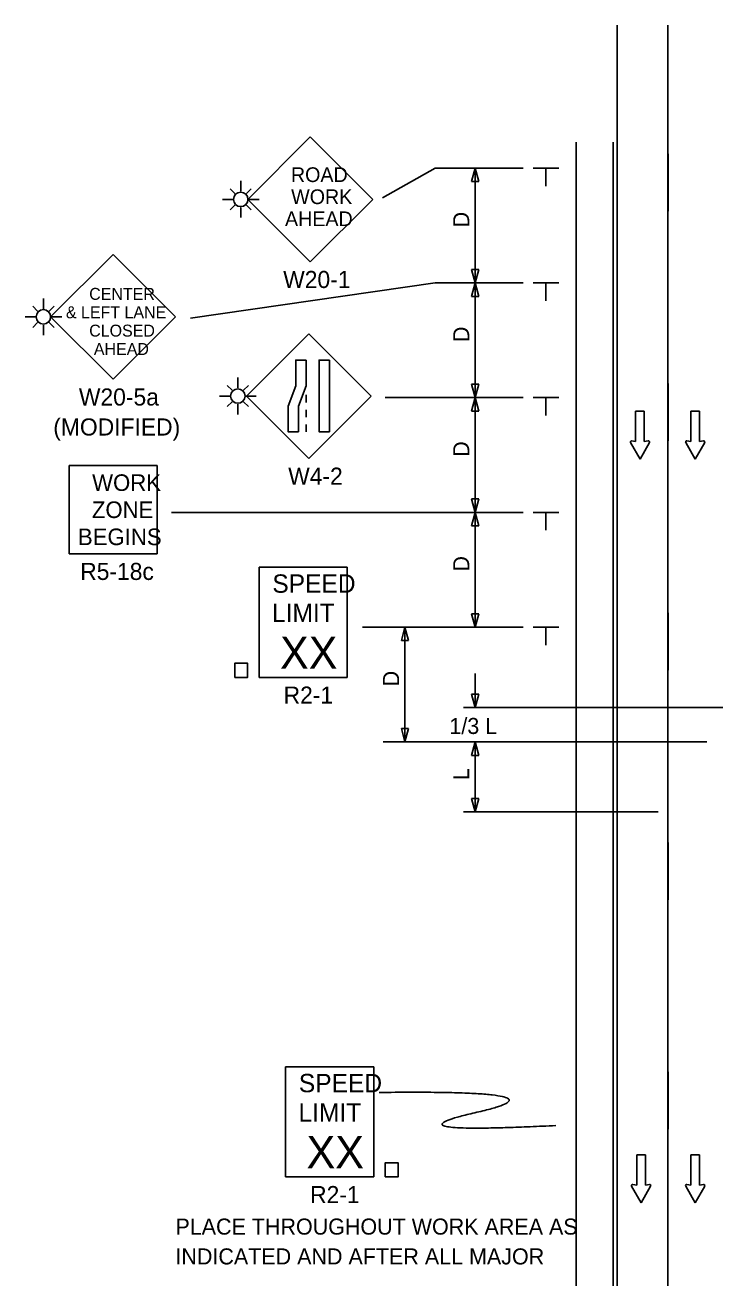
# Model space of a CAD drawing. Extents: x 16038 to 19504, y 5920 to 8321.
# Drawn here: x 16730 to 17031, y 7716 to 8262 of the extents above; entities that cross this region are included whole.
import ezdxf

# ---------------------------------------------------------------- set-up
doc = ezdxf.new("R2010")
doc.units = 0
for name, color, linetype in [('ALI_LEGAL_EX', 7, 'Continuous'), ('MT_SCRATCH_LEVEL_E', 7, 'Continuous'), ('PAVT_EDGE_EX', 7, 'Continuous'), ('TRAFFIC_SIGNS_PR', 7, 'Continuous'), ('TYPICAL_TEXT_DIMEN_PR', 7, 'Continuous')]:
    doc.layers.add(name, color=color, linetype=linetype)

msp = doc.modelspace()

# ---------------------------------------------------------------- linework, layer by layer
at = {"layer": 'ALI_LEGAL_EX'}
for points in [[(17010.3, 8181.21), (17010.3, 8206.21)], [(17010.3, 8081.21), (17010.3, 8106.21)], [(17010.3, 7981.21), (17010.3, 8006.21)], [(17010.3, 7881.21), (17010.3, 7906.21)], [(17010.3, 7781.21), (17010.3, 7806.21)]]:
    msp.add_lwpolyline(points, dxfattribs=at)
at = {"layer": 'MT_SCRATCH_LEVEL_E'}
for p, q in [((16999.9, 8094.07), (16996.16, 8094.07)), ((16996.16, 8094.07), (16996.16, 8080.81)), ((16999.9, 8094.07), (16996.16, 8094.07)), ((16996.16, 8094.07), (16996.16, 8080.81)), ((16999.9, 8080.81), (16999.9, 8094.07)), ((16999.9, 8080.81), (16999.9, 8094.07)), ((17023.97, 8094.07), (17020.23, 8094.07)), ((17020.23, 8094.07), (17020.23, 8080.81)), ((17023.97, 8094.07), (17020.23, 8094.07)), ((17020.23, 8094.07), (17020.23, 8080.81)), ((17023.97, 8094.07), (17020.23, 8094.07)), ((17020.23, 8094.07), (17020.23, 8080.81)), ((17023.97, 8094.07), (17020.23, 8094.07)), ((17020.23, 8094.07), (17020.23, 8080.81)), ((17023.97, 8080.81), (17023.97, 8094.07)), ((17023.97, 8080.81), (17023.97, 8094.07)), ((17023.97, 8080.81), (17023.97, 8094.07)), ((17023.97, 8080.81), (17023.97, 8094.07)), ((16993.9, 8080.44), (16998.05, 8073.2)), ((16993.9, 8080.44), (16998.05, 8073.2)), ((16996.16, 8080.81), (16994.38, 8081.12)), ((16996.16, 8080.81), (16994.38, 8081.12)), ((16998.05, 8073.2), (17002.16, 8080.44)), ((16998.05, 8073.2), (17002.16, 8080.44)), ((17001.68, 8081.12), (16999.9, 8080.81)), ((17001.68, 8081.12), (16999.9, 8080.81)), ((17017.97, 8080.44), (17022.12, 8073.2)), ((17017.97, 8080.44), (17022.12, 8073.2)), ((17017.97, 8080.44), (17022.12, 8073.2)), ((17017.97, 8080.44), (17022.12, 8073.2)), ((17020.23, 8080.81), (17018.45, 8081.12)), ((17020.23, 8080.81), (17018.45, 8081.12)), ((17020.23, 8080.81), (17018.45, 8081.12)), ((17020.23, 8080.81), (17018.45, 8081.12)), ((17022.12, 8073.2), (17026.23, 8080.44)), ((17022.12, 8073.2), (17026.23, 8080.44)), ((17022.12, 8073.2), (17026.23, 8080.44)), ((17022.12, 8073.2), (17026.23, 8080.44)), ((17025.75, 8081.12), (17023.97, 8080.81)), ((17025.75, 8081.12), (17023.97, 8080.81)), ((17025.75, 8081.12), (17023.97, 8080.81)), ((17025.75, 8081.12), (17023.97, 8080.81)), ((17000.4, 7770.06), (16996.66, 7770.06)), ((16996.66, 7770.06), (16996.66, 7756.81)), ((17000.4, 7770.06), (16996.66, 7770.06)), ((16996.66, 7770.06), (16996.66, 7756.81)), ((17000.4, 7756.81), (17000.4, 7770.06)), ((17000.4, 7756.81), (17000.4, 7770.06)), ((17023.97, 7770.06), (17020.23, 7770.06)), ((17020.23, 7770.06), (17020.23, 7756.81)), ((17023.97, 7770.06), (17020.23, 7770.06)), ((17020.23, 7770.06), (17020.23, 7756.81)), ((17023.97, 7756.81), (17023.97, 7770.06)), ((17023.97, 7756.81), (17023.97, 7770.06)), ((16994.4, 7756.44), (16998.55, 7749.2)), ((16994.4, 7756.44), (16998.55, 7749.2)), ((16996.66, 7756.81), (16994.88, 7757.12)), ((16996.66, 7756.81), (16994.88, 7757.12)), ((16998.55, 7749.2), (17002.66, 7756.44)), ((16998.55, 7749.2), (17002.66, 7756.44)), ((17002.18, 7757.12), (17000.4, 7756.81)), ((17002.18, 7757.12), (17000.4, 7756.81)), ((17017.97, 7756.44), (17022.12, 7749.2)), ((17017.97, 7756.44), (17022.12, 7749.2)), ((17020.23, 7756.81), (17018.45, 7757.12)), ((17020.23, 7756.81), (17018.45, 7757.12)), ((17022.12, 7749.2), (17026.23, 7756.44)), ((17022.12, 7749.2), (17026.23, 7756.44)), ((17025.75, 7757.12), (17023.97, 7756.81)), ((17025.75, 7757.12), (17023.97, 7756.81))]:
    msp.add_line(p, q, dxfattribs=at)
for centre, start, end in [((16994.31, 8080.67), 80.0362, 209.7731), ((16994.31, 8080.67), 80.0362, 209.7731), ((17001.75, 8080.67), 330.4248, 99.9638), ((17001.75, 8080.67), 330.4248, 99.9638), ((17018.38, 8080.67), 80.0362, 209.7731), ((17018.38, 8080.67), 80.0362, 209.7731), ((17018.38, 8080.67), 80.0362, 209.7731), ((17018.38, 8080.67), 80.0362, 209.7731), ((17025.82, 8080.67), 330.4248, 99.9638), ((17025.82, 8080.67), 330.4248, 99.9638), ((17025.82, 8080.67), 330.4248, 99.9638), ((17025.82, 8080.67), 330.4248, 99.9638), ((16994.81, 7756.66), 80.0362, 209.7731), ((16994.81, 7756.66), 80.0362, 209.7731), ((17002.25, 7756.66), 330.4248, 99.9638), ((17002.25, 7756.66), 330.4248, 99.9638), ((17018.38, 7756.66), 80.0362, 209.7731), ((17018.38, 7756.66), 80.0362, 209.7731), ((17025.82, 7756.66), 330.4248, 99.9638), ((17025.82, 7756.66), 330.4248, 99.9638)]:
    msp.add_arc(centre, 0.463, start, end, dxfattribs=at)
at = {"layer": 'PAVT_EDGE_EX'}
for p, q in [((16988.15, 8262.34), (16988.15, 7433.15)), ((17010.15, 8262.34), (17010.15, 7433.15)), ((16970.3, 8211.37), (16970.3, 7379.53)), ((16986.3, 8211.37), (16986.3, 7379.53))]:
    msp.add_line(p, q, dxfattribs=at)
at = {"layer": 'TRAFFIC_SIGNS_PR'}
for p, q in [((16854.39, 8213.58), (16827.2, 8186.39)), ((16881.58, 8186.39), (16854.39, 8213.58)), ((16821.54, 8188.91), (16819.43, 8191.02)), ((16824.05, 8189.95), (16824.05, 8194.45)), ((16826.56, 8188.91), (16828.67, 8191.02)), ((16820.9, 8186.39), (16816.06, 8186.39)), ((16821.54, 8183.88), (16819.43, 8181.77)), ((16826.56, 8183.88), (16828.67, 8181.77)), ((16827.2, 8186.39), (16854.39, 8159.21)), ((16827.2, 8186.39), (16832.09, 8186.39)), ((16854.39, 8159.21), (16881.58, 8186.39)), ((16824.05, 8178.43), (16824.05, 8182.84)), ((16768.41, 8162.37), (16741.22, 8135.18)), ((16795.59, 8135.18), (16768.41, 8162.37)), ((16738.07, 8138.74), (16738.07, 8143.24)), ((16734.91, 8135.18), (16730.08, 8135.18)), ((16735.55, 8137.69), (16733.44, 8139.8)), ((16740.58, 8137.69), (16742.69, 8139.8)), ((16741.22, 8135.18), (16768.41, 8107.99)), ((16741.22, 8135.18), (16746.1, 8135.18)), ((16741.22, 8135.18), (16768.41, 8107.99)), ((16768.41, 8107.99), (16795.59, 8135.18)), ((16735.55, 8132.67), (16733.44, 8130.56)), ((16738.07, 8127.22), (16738.07, 8131.63)), ((16740.58, 8132.67), (16742.69, 8130.56)), ((16853.78, 8127.8), (16826.63, 8100.65)), ((16880.93, 8100.65), (16853.78, 8127.8)), ((16822.8, 8104.24), (16822.8, 8108.74)), ((16820.29, 8103.19), (16818.18, 8105.3)), ((16825.31, 8103.19), (16827.42, 8105.3)), ((16819.65, 8100.68), (16814.81, 8100.68)), ((16820.29, 8098.17), (16818.18, 8096.06)), ((16822.8, 8092.71), (16822.8, 8097.13)), ((16825.31, 8098.17), (16827.42, 8096.06)), ((16825.96, 8100.68), (16830.84, 8100.68)), ((16826.63, 8100.65), (16853.78, 8073.49)), ((16852.53, 8101.14), (16852.53, 8097.94)), ((16853.78, 8073.49), (16880.93, 8100.65)), ((16852.53, 8094.74), (16852.53, 8091.54)), ((16852.53, 8088.34), (16852.53, 8085.14)), ((16749.31, 8031.98), (16749.31, 8070.38)), ((16749.31, 8070.38), (16787.71, 8070.38)), ((16787.71, 8031.98), (16787.71, 8070.38)), ((16749.31, 8031.98), (16787.71, 8031.98)), ((16832.07, 8026.1), (16870.47, 8026.1)), ((16832.07, 7978.1), (16832.07, 8026.1)), ((16870.47, 7978.1), (16870.47, 8026.1)), ((16832.07, 7978.1), (16870.47, 7978.1)), ((16843.62, 7808.45), (16882.02, 7808.45)), ((16843.62, 7760.45), (16843.62, 7808.45)), ((16882.02, 7760.45), (16882.02, 7808.45)), ((16843.62, 7760.45), (16882.02, 7760.45))]:
    msp.add_line(p, q, dxfattribs=at)
for points in [[(16852.53, 8116.38), (16852.53, 8105.2), (16849.19, 8096.32), (16849.19, 8085.14), (16844.69, 8085.14), (16844.69, 8096.32), (16848.04, 8105.2), (16848.04, 8116.38)], [(16862.67, 8116.38), (16862.67, 8085.14), (16858.18, 8085.14), (16858.18, 8116.38)], [(16821.46, 7978.1), (16827.05, 7978.1), (16827.05, 7984.27), (16821.46, 7984.27)], [(16887.04, 7760.45), (16892.63, 7760.45), (16892.63, 7766.63), (16887.04, 7766.63)]]:
    msp.add_lwpolyline(points, close=True, dxfattribs=at)
for centre in [(16824.05, 8186.39), (16738.07, 8135.18), (16822.8, 8100.68)]:
    msp.add_circle(centre, 3.15, dxfattribs=at)
msp.add_open_spline([(16884.36, 7797.22), (16969.4, 7798.24), (16884.38, 7778.89), (16961.38, 7782.81)], degree=2, dxfattribs=at)
at = {"layer": 'TYPICAL_TEXT_DIMEN_PR'}
for p, q in [((16908.76, 8199.98), (16885.9, 8187.11)), ((16908.76, 8199.98), (16947.2, 8199.98)), ((16924.63, 8194.11), (16926.2, 8199.98)), ((16924.63, 8194.11), (16926.2, 8199.98)), ((16926.2, 8199.98), (16927.77, 8194.11)), ((16926.2, 8199.98), (16927.77, 8194.11)), ((16926.2, 8149.98), (16926.2, 8199.98)), ((16951.45, 8199.98), (16962.7, 8199.98)), ((16951.45, 8199.98), (16962.7, 8199.98)), ((16957.08, 8199.98), (16957.08, 8192.19)), ((16957.08, 8199.98), (16957.08, 8192.19)), ((16926.2, 8194.11), (16924.63, 8194.11)), ((16926.2, 8194.11), (16924.63, 8194.11)), ((16927.77, 8194.11), (16926.2, 8194.11)), ((16927.77, 8194.11), (16926.2, 8194.11)), ((16926.2, 8149.98), (16924.63, 8155.84)), ((16924.63, 8155.84), (16926.2, 8155.84)), ((16926.2, 8149.98), (16924.63, 8155.84)), ((16924.63, 8155.84), (16926.2, 8155.84)), ((16926.2, 8155.84), (16927.77, 8155.84)), ((16927.77, 8155.84), (16926.2, 8149.98)), ((16926.2, 8155.84), (16927.77, 8155.84)), ((16927.77, 8155.84), (16926.2, 8149.98)), ((16908.76, 8149.98), (16802.1, 8134.61)), ((16908.76, 8149.98), (16947.2, 8149.98)), ((16924.63, 8144.11), (16926.2, 8149.98)), ((16924.63, 8144.11), (16926.2, 8149.98)), ((16926.2, 8149.98), (16927.77, 8144.11)), ((16926.2, 8149.98), (16927.77, 8144.11)), ((16926.2, 8099.98), (16926.2, 8149.98)), ((16951.45, 8149.98), (16962.7, 8149.98)), ((16957.08, 8149.98), (16957.08, 8142.19)), ((16926.2, 8144.11), (16924.63, 8144.11)), ((16926.2, 8144.11), (16924.63, 8144.11)), ((16927.77, 8144.11), (16926.2, 8144.11)), ((16927.77, 8144.11), (16926.2, 8144.11)), ((16926.2, 8099.98), (16924.63, 8105.84)), ((16924.63, 8105.84), (16926.2, 8105.84)), ((16926.2, 8105.84), (16927.77, 8105.84)), ((16927.77, 8105.84), (16926.2, 8099.98)), ((16886.97, 8099.98), (16947.2, 8099.98)), ((16924.63, 8094.11), (16926.2, 8099.98)), ((16924.63, 8094.11), (16926.2, 8099.98)), ((16926.2, 8099.98), (16927.77, 8094.11)), ((16926.2, 8099.98), (16927.77, 8094.11)), ((16926.2, 8049.98), (16926.2, 8099.98)), ((16951.45, 8099.98), (16962.7, 8099.98)), ((16951.45, 8099.98), (16962.7, 8099.98)), ((16957.08, 8099.98), (16957.08, 8092.19)), ((16957.08, 8099.98), (16957.08, 8092.19)), ((16926.2, 8094.11), (16924.63, 8094.11)), ((16926.2, 8094.11), (16924.63, 8094.11)), ((16927.77, 8094.11), (16926.2, 8094.11)), ((16927.77, 8094.11), (16926.2, 8094.11)), ((16926.2, 8049.98), (16924.63, 8055.84)), ((16924.63, 8055.84), (16926.2, 8055.84)), ((16926.2, 8049.98), (16924.63, 8055.84)), ((16924.63, 8055.84), (16926.2, 8055.84)), ((16926.2, 8055.84), (16927.77, 8055.84)), ((16927.77, 8055.84), (16926.2, 8049.98)), ((16926.2, 8055.84), (16927.77, 8055.84)), ((16927.77, 8055.84), (16926.2, 8049.98)), ((16793.89, 8049.98), (16947.2, 8049.98)), ((16924.63, 8044.11), (16926.2, 8049.98)), ((16924.63, 8044.11), (16926.2, 8049.98)), ((16926.2, 8049.98), (16927.77, 8044.11)), ((16926.2, 7999.98), (16926.2, 8049.98)), ((16926.2, 8049.98), (16927.77, 8044.11)), ((16926.2, 7999.98), (16926.2, 8049.98)), ((16951.45, 8049.98), (16962.7, 8049.98)), ((16957.08, 8049.98), (16957.08, 8042.19)), ((16926.2, 8044.11), (16924.63, 8044.11)), ((16926.2, 8044.11), (16924.63, 8044.11)), ((16927.77, 8044.11), (16926.2, 8044.11)), ((16927.77, 8044.11), (16926.2, 8044.11)), ((16926.2, 7999.98), (16924.63, 8005.84)), ((16924.63, 8005.84), (16926.2, 8005.84)), ((16926.2, 7999.98), (16924.63, 8005.84)), ((16924.63, 8005.84), (16926.2, 8005.84)), ((16926.2, 8005.84), (16927.77, 8005.84)), ((16927.77, 8005.84), (16926.2, 7999.98)), ((16926.2, 8005.84), (16927.77, 8005.84)), ((16927.77, 8005.84), (16926.2, 7999.98)), ((16877.12, 7999.98), (16947.2, 7999.98)), ((16894.05, 7994.11), (16895.62, 7999.98)), ((16895.62, 7999.98), (16897.19, 7994.11)), ((16895.62, 7949.98), (16895.62, 7999.98)), ((16951.45, 7999.98), (16962.7, 7999.98)), ((16957.08, 7999.98), (16957.08, 7992.19)), ((16895.62, 7994.11), (16894.05, 7994.11)), ((16897.19, 7994.11), (16895.62, 7994.11)), ((16926.2, 7979.82), (16926.2, 7964.9)), ((16926.2, 7964.9), (16924.63, 7970.76)), ((16924.63, 7970.76), (16926.2, 7970.76)), ((16926.2, 7964.9), (16924.63, 7970.76)), ((16924.63, 7970.76), (16926.2, 7970.76)), ((16926.2, 7970.76), (16927.77, 7970.76)), ((16927.77, 7970.76), (16926.2, 7964.9)), ((16926.2, 7970.76), (16927.77, 7970.76)), ((16927.77, 7970.76), (16926.2, 7964.9)), ((16921.2, 7964.9), (17071.43, 7964.9)), ((16895.62, 7949.98), (16894.05, 7955.84)), ((16894.05, 7955.84), (16895.62, 7955.84)), ((16895.62, 7955.84), (16897.19, 7955.84)), ((16897.19, 7955.84), (16895.62, 7949.98)), ((17027.11, 7949.98), (16886.11, 7949.98)), ((16924.63, 7944.11), (16926.2, 7949.98)), ((16926.2, 7919.44), (16926.2, 7949.98)), ((16926.2, 7949.98), (16927.77, 7944.11)), ((16926.2, 7944.11), (16924.63, 7944.11)), ((16927.77, 7944.11), (16926.2, 7944.11)), ((16926.2, 7919.44), (16924.63, 7925.3)), ((16924.63, 7925.3), (16926.2, 7925.3)), ((16926.2, 7925.3), (16927.77, 7925.3)), ((16927.77, 7925.3), (16926.2, 7919.44)), ((16921.2, 7919.44), (17006.03, 7919.44))]:
    msp.add_line(p, q, dxfattribs=at)

# ---------------------------------------------------------------- texts
at = {"layer": 'TRAFFIC_SIGNS_PR'}
for s, height, p in [('ROAD', 6.408, (16845.92, 8193.94)), ('WORK', 6.408, (16846.03, 8184.33)), ('AHEAD', 6.408, (16843.34, 8174.72)), ('W20-1', 7.449, (16842.55, 8147.75)), ('CENTER', 5.206, (16758.03, 8142.6)), ('& LEFT LANE', 5.2065, (16747.88, 8134.59)), ('CLOSED', 5.206, (16758.03, 8126.58)), ('AHEAD', 5.206, (16760.06, 8118.57)), ('W20-5a', 7.449, (16753.53, 8096.54)), ('(MODIFIED)', 7.449, (16742.37, 8083.48)), ('W4-2', 7.44, (16844.74, 8062.05)), ('WORK', 7.217, (16759.31, 8059.34)), ('ZONE', 7.217, (16759.19, 8047.53)), ('BEGINS', 7.217, (16753.12, 8035.72)), ('R5-18c', 7.44, (16754.12, 8020.54)), ('SPEED', 8, (16837.84, 8014.96)), ('LIMIT', 8, (16837.68, 8002.16)), ('XX', 14.031, (16841.18, 7981.86)), ('R2-1', 7.44, (16842.75, 7966.66)), ('SPEED', 8, (16849.39, 7797.32)), ('LIMIT', 8, (16849.23, 7784.52)), ('XX', 14.031, (16852.73, 7764.21)), ('R2-1', 7.44, (16854.3, 7749.01)), ('PLACE THROUGHOUT WORK AREA AS', 7, (16795.6, 7735.28)), ('INDICATED AND AFTER ALL MAJOR', 7, (16795.6, 7722.28))]:
    msp.add_text(s, height=height, dxfattribs=at).set_placement(p)
at = {"layer": 'TYPICAL_TEXT_DIMEN_PR'}
for s, p in [('D', (16923.64, 8174.19)), ('D', (16923.64, 8174.19)), ('D', (16923.64, 8124.19)), ('D', (16923.64, 8124.19)), ('D', (16923.64, 8074.19)), ('D', (16923.64, 8074.19)), ('D', (16923.64, 8024.19)), ('D', (16923.64, 8024.19)), ('D', (16893.06, 7974.19)), ('L', (16923.64, 7933.31))]:
    msp.add_text(s, height=7, rotation=90, dxfattribs=at).set_placement(p)
msp.add_text('1/3 L', height=7, dxfattribs=at).set_placement((16914.99, 7953.43))
msp.add_text('1/3 L', height=7, dxfattribs=at).set_placement((16914.99, 7953.43))

doc.saveas('drawing.dxf')
